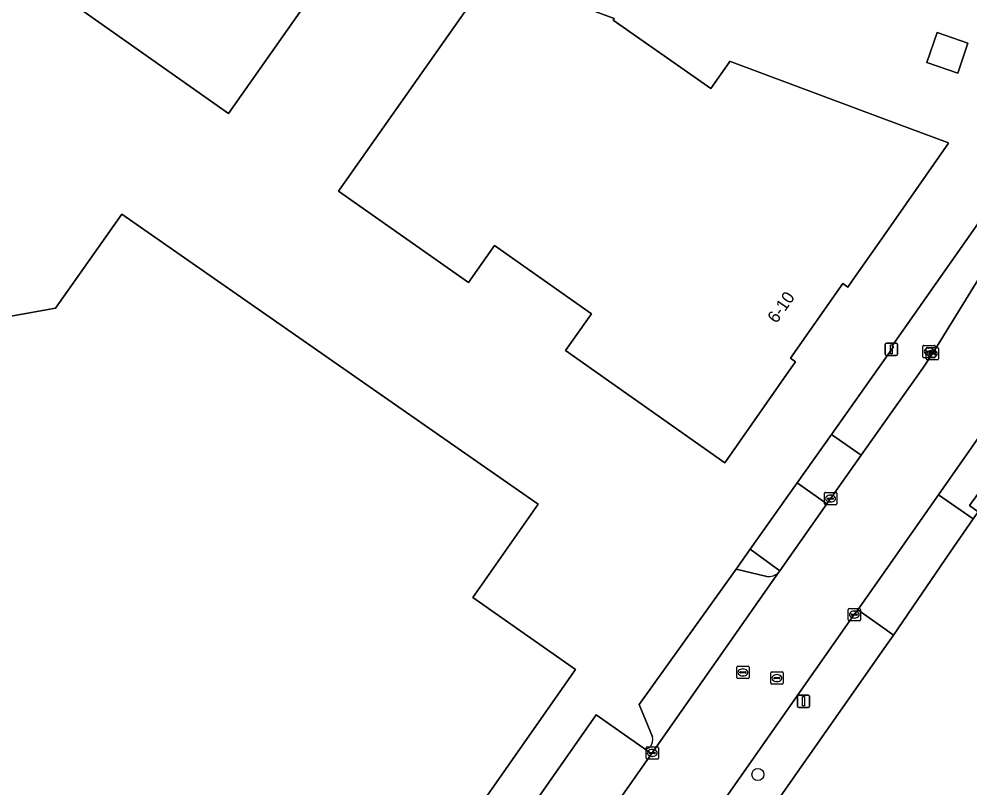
# Model space of a CAD drawing. Extents: x 155018 to 156648, y 383979 to 385733.
# Drawn here: x 155429.7 to 155506.9, y 385085.5 to 385148 of the extents above; entities that cross this region are included whole.
import ezdxf

# ---------------------------------------------------------------- set-up
doc = ezdxf.new("R2010")
doc.units = 0
for name, color, linetype in [('IMGEO_Boom', 7, 'Continuous'), ('IMGEO_Erf', 7, 'Continuous'), ('IMGEO_Kolk', 7, 'Continuous'), ('IMGEO_Lichtmast', 7, 'Continuous'), ('IMGEO_Pand', 7, 'Continuous'), ('IMGEO_Pand_nummerreeks', 7, 'Continuous'), ('IMGEO_Parkeervlak_open', 7, 'Continuous'), ('IMGEO_Rijbaan_lokaal_gesloten', 7, 'Continuous'), ('IMGEO_Rijbaan_lokaal_open', 7, 'Continuous'), ('IMGEO_Rioolput', 7, 'Continuous'), ('IMGEO_Voetpad_open', 7, 'Continuous')]:
    doc.layers.add(name, color=color, linetype=linetype)

msp = doc.modelspace()

# ---------------------------------------------------------------- linework, layer by layer
at = {"layer": 'IMGEO_Boom'}
msp.add_circle((155489.766, 385086.611), 0.489, dxfattribs=at)
at = {"layer": 'IMGEO_Erf'}
for points in [[(155413.901, 385195.202), (155443.274, 385174.657), (155442.008, 385172.848), (155454.266, 385164.273), (155459.175, 385158.044), (155446.72, 385140.342), (155440.509, 385144.723), (155428.297, 385153.343), (155424.544, 385148.026), (155385.157, 385092.221), (155368.632, 385103.714), (155368.071, 385102.911), (155349.266, 385116.068), (155349.893, 385116.961), (155349.496, 385119.02), (155348.617, 385119.628), (155359.431, 385135.082), (155364.489, 385131.542), (155367.766, 385129.249), (155370.632, 385133.346)], [(155468.14, 385151.739), (155478.07, 385148.075), (155478.004, 385147.93), (155485.935, 385142.376), (155487.428, 385144.488), (155487.454, 385144.588), (155500, 385139.914), (155505.174, 385137.986), (155505.266, 385137.927), (155500, 385130.399), (155497.444, 385126.745), (155497.088, 385126.236), (155496.678, 385126.524), (155492.417, 385120.452), (155492.827, 385120.164), (155492.475, 385119.66), (155487.089, 385111.95), (155474.126, 385121.065), (155476.237, 385124.066), (155468.354, 385129.61), (155466.243, 385126.609), (155455.672, 385134.024)], [(155504.353, 385146.913), (155506.838, 385146.045), (155506.025, 385143.622), (155503.492, 385144.492)]]:
    msp.add_lwpolyline(points, close=True, dxfattribs=at)
for points in [[(155481.197, 385089.662), (155480.122, 385092.288), (155488.002, 385103.313), (155488.181, 385103.567), (155489.14, 385104.923), (155492.958, 385110.322), (155495.738, 385114.252), (155500, 385120.251), (155500.792, 385121.366), (155500.688, 385121.46), (155508.553, 385132.633), (155507.992, 385133.028), (155510.135, 385136.111), (155510.234, 385136.1), (155510.941, 385137.798), (155512.006, 385141.006), (155512.546, 385141.983), (155514.242, 385146.673), (155513.774, 385146.868), (155529.193, 385190.291)], [(155411.431, 385120.683), (155432.666, 385124.506), (155438.045, 385132.168), (155467.798, 385111.439), (155471.901, 385108.581), (155466.588, 385100.985), (155474.93, 385095.15), (155457.22, 385069.83), (155453.46, 385069.27), (155453.5, 385068.76)], [(155508.732, 385110.886), (155506.969, 385108.464), (155507.669, 385107.967), (155507.272, 385107.392), (155505.402, 385104.686), (155500.791, 385097.946), (155500, 385096.817), (155478.381, 385065.973), (155465.216, 385047.189), (155455.905, 385033.942)], [(155469.031, 385072.592), (155465.262, 385075.236), (155476.621, 385091.468), (155480.435, 385088.767)]]:
    msp.add_lwpolyline(points, dxfattribs=at)
for centre, radius, start, end in [((155480.307, 385089.443), 0.917, 322.49003, 13.81442), ((155480.671, 385089.151), 0.45, 238.43948, 323.84909)]:
    msp.add_arc(centre, radius, start, end, dxfattribs=at)
at = {"layer": 'IMGEO_Kolk'}
for p, q in [((155503.188, 385120.565), (155503.188, 385121.417)), ((155503.263, 385121.491), (155504.115, 385121.491)), ((155503.44, 385120.389), (155503.44, 385121.241)), ((155503.447, 385120.985), (155503.447, 385120.997)), ((155503.885, 385120.948), (155503.487, 385120.948)), ((155503.49, 385121.034), (155503.888, 385121.034)), ((155503.515, 385121.315), (155504.367, 385121.315)), ((155503.676, 385121.271), (155503.701, 385121.271)), ((155503.699, 385120.809), (155503.699, 385120.821)), ((155504.137, 385120.772), (155503.739, 385120.772)), ((155503.742, 385120.858), (155504.14, 385120.858)), ((155503.928, 385121.095), (155503.953, 385121.095)), ((155503.931, 385120.997), (155503.931, 385120.985)), ((155504.183, 385120.821), (155504.183, 385120.809)), ((155504.189, 385121.417), (155504.189, 385120.565)), ((155504.441, 385121.241), (155504.441, 385120.389)), ((155504.115, 385120.491), (155503.263, 385120.491)), ((155504.367, 385120.315), (155503.515, 385120.315)), ((155503.699, 385120.711), (155503.674, 385120.711)), ((155503.951, 385120.535), (155503.926, 385120.535)), ((155495.176, 385108.615), (155495.176, 385109.467)), ((155495.251, 385109.541), (155496.103, 385109.541)), ((155495.664, 385109.321), (155495.689, 385109.321)), ((155496.177, 385109.467), (155496.177, 385108.615)), ((155496.103, 385108.541), (155495.251, 385108.541)), ((155495.435, 385109.035), (155495.435, 385109.047)), ((155495.873, 385108.998), (155495.475, 385108.998)), ((155495.478, 385109.084), (155495.876, 385109.084)), ((155495.687, 385108.761), (155495.662, 385108.761)), ((155495.919, 385109.047), (155495.919, 385109.035)), ((155497.104, 385099.178), (155497.104, 385100.03)), ((155497.179, 385100.104), (155498.031, 385100.104)), ((155498.105, 385100.03), (155498.105, 385099.178)), ((155497.363, 385099.598), (155497.363, 385099.61)), ((155497.801, 385099.561), (155497.403, 385099.561)), ((155497.406, 385099.647), (155497.804, 385099.647)), ((155497.615, 385099.324), (155497.59, 385099.324)), ((155497.592, 385099.884), (155497.617, 385099.884)), ((155497.847, 385099.61), (155497.847, 385099.598)), ((155498.031, 385099.104), (155497.179, 385099.104)), ((155480.678, 385087.935), (155480.678, 385088.787)), ((155480.753, 385088.861), (155481.605, 385088.861)), ((155480.937, 385088.355), (155480.937, 385088.367)), ((155480.98, 385088.404), (155481.378, 385088.404)), ((155481.166, 385088.641), (155481.191, 385088.641)), ((155481.421, 385088.367), (155481.421, 385088.355)), ((155481.679, 385088.787), (155481.679, 385087.935)), ((155481.605, 385087.861), (155480.753, 385087.861)), ((155481.375, 385088.318), (155480.977, 385088.318)), ((155481.189, 385088.081), (155481.164, 385088.081))]:
    msp.add_line(p, q, dxfattribs=at)
for points in [[(155503.188, 385120.565), (155503.188, 385121.417)], [(155503.263, 385121.491), (155504.115, 385121.491)], [(155503.44, 385120.389), (155503.44, 385121.241)], [(155503.515, 385121.315), (155504.367, 385121.315)], [(155504.189, 385121.417), (155504.189, 385120.565)], [(155504.441, 385121.241), (155504.441, 385120.389)], [(155504.115, 385120.491), (155503.263, 385120.491)], [(155504.367, 385120.315), (155503.515, 385120.315)], [(155495.176, 385108.615), (155495.176, 385109.467)], [(155495.251, 385109.541), (155496.103, 385109.541)], [(155496.177, 385109.467), (155496.177, 385108.615)], [(155496.103, 385108.541), (155495.251, 385108.541)], [(155497.104, 385099.178), (155497.104, 385100.03)], [(155497.179, 385100.104), (155498.031, 385100.104)], [(155498.105, 385100.03), (155498.105, 385099.178)], [(155498.031, 385099.104), (155497.179, 385099.104)], [(155480.678, 385087.935), (155480.678, 385088.787)], [(155480.753, 385088.861), (155481.605, 385088.861)], [(155481.679, 385088.787), (155481.679, 385087.935)], [(155481.605, 385087.861), (155480.753, 385087.861)]]:
    msp.add_lwpolyline(points, dxfattribs=at)
for centre, radius, start, end in [((155503.265, 385121.415), 0.0765, 91.55205, 178.44795), ((155503.265, 385121.415), 0.0765, 91.55205, 178.44795), ((155503.517, 385121.239), 0.0765, 91.55205, 178.44795), ((155503.517, 385121.239), 0.0765, 91.55205, 178.44795), ((155503.487, 385120.994), 0.0403, 85.87752, 175.75265), ((155503.484, 385120.984), 0.0366, 178.93798, 274.71019), ((155503.739, 385120.818), 0.0403, 85.87752, 175.75265), ((155503.736, 385120.808), 0.0366, 178.93798, 274.71019), ((155503.888, 385120.991), 0.043, 264.86636, 352.45326), ((155503.892, 385120.996), 0.0386, 1.73085, 96.63898), ((155504.113, 385121.415), 0.0765, 1.55205, 88.44795), ((155504.113, 385121.415), 0.0765, 1.55205, 88.44795), ((155504.14, 385120.815), 0.043, 264.86636, 352.45326), ((155504.144, 385120.82), 0.0386, 1.73085, 96.63898), ((155504.365, 385121.239), 0.0765, 1.55205, 88.44795), ((155504.365, 385121.239), 0.0765, 1.55205, 88.44795), ((155503.265, 385120.567), 0.0765, 181.55205, 268.44795), ((155503.265, 385120.567), 0.0765, 181.55205, 268.44795), ((155503.517, 385120.391), 0.0765, 181.55205, 268.44795), ((155503.517, 385120.391), 0.0765, 181.55205, 268.44795), ((155504.113, 385120.567), 0.0765, 271.55205, 358.44795), ((155504.113, 385120.567), 0.0765, 271.55205, 358.44795), ((155504.365, 385120.391), 0.0765, 271.55205, 358.44795), ((155504.365, 385120.391), 0.0765, 271.55205, 358.44795), ((155495.253, 385109.465), 0.0765, 91.55205, 178.44795), ((155495.253, 385109.465), 0.0765, 91.55205, 178.44795), ((155496.101, 385109.465), 0.0765, 1.55205, 88.44795), ((155496.101, 385109.465), 0.0765, 1.55205, 88.44795), ((155495.253, 385108.617), 0.0765, 181.55205, 268.44795), ((155495.253, 385108.617), 0.0765, 181.55205, 268.44795), ((155495.475, 385109.044), 0.0403, 85.87752, 175.75265), ((155495.472, 385109.034), 0.0366, 178.93798, 274.71019), ((155495.876, 385109.041), 0.043, 264.86636, 352.45326), ((155495.88, 385109.046), 0.0386, 1.73085, 96.63898), ((155496.101, 385108.617), 0.0765, 271.55205, 358.44795), ((155496.101, 385108.617), 0.0765, 271.55205, 358.44795), ((155497.181, 385100.028), 0.0765, 91.55205, 178.44795), ((155497.181, 385100.028), 0.0765, 91.55205, 178.44795), ((155498.029, 385100.028), 0.0765, 1.55205, 88.44795), ((155498.029, 385100.028), 0.0765, 1.55205, 88.44795), ((155497.181, 385099.18), 0.0765, 181.55205, 268.44795), ((155497.181, 385099.18), 0.0765, 181.55205, 268.44795), ((155497.403, 385099.607), 0.0403, 85.87752, 175.75265), ((155497.4, 385099.597), 0.0366, 178.93798, 274.71019), ((155497.804, 385099.604), 0.043, 264.86636, 352.45326), ((155497.808, 385099.609), 0.0386, 1.73085, 96.63898), ((155498.029, 385099.18), 0.0765, 271.55205, 358.44795), ((155498.029, 385099.18), 0.0765, 271.55205, 358.44795), ((155480.755, 385088.785), 0.0765, 91.55205, 178.44795), ((155480.755, 385088.785), 0.0765, 91.55205, 178.44795), ((155480.977, 385088.364), 0.0403, 85.87752, 175.75265), ((155480.974, 385088.354), 0.0366, 178.93798, 274.71019), ((155481.378, 385088.361), 0.043, 264.86636, 352.45326), ((155481.382, 385088.366), 0.0386, 1.73085, 96.63898), ((155481.603, 385088.785), 0.0765, 1.55205, 88.44795), ((155481.603, 385088.785), 0.0765, 1.55205, 88.44795), ((155480.755, 385087.937), 0.0765, 181.55205, 268.44795), ((155480.755, 385087.937), 0.0765, 181.55205, 268.44795), ((155481.603, 385087.937), 0.0765, 271.55205, 358.44795), ((155481.603, 385087.937), 0.0765, 271.55205, 358.44795)]:
    msp.add_arc(centre, radius, start, end, dxfattribs=at)
for centre, major_axis, ratio, start_param, end_param in [((155503.675, 385120.991), (-0.387, 0.002), 0.722429, 4.712389, 7.853982), ((155503.927, 385120.815), (-0.387, 0.002), 0.722429, 4.712389, 7.853982), ((155503.7, 385120.991), (-0.39, 0.002), 0.717154, 1.570796, 4.712389), ((155503.952, 385120.815), (-0.39, 0.002), 0.717154, 1.570796, 4.712389), ((155495.663, 385109.041), (-0.387, 0.002), 0.722429, 4.712389, 7.853982), ((155495.688, 385109.041), (-0.39, 0.002), 0.717154, 1.570796, 4.712389), ((155497.591, 385099.604), (-0.387, 0.002), 0.722429, 4.712389, 7.853982), ((155497.616, 385099.604), (-0.39, 0.002), 0.717154, 1.570796, 4.712389), ((155481.165, 385088.361), (-0.387, 0.002), 0.722429, 4.712389, 7.853982), ((155481.19, 385088.361), (-0.39, 0.002), 0.717154, 1.570796, 4.712389)]:
    msp.add_ellipse(centre, major_axis=major_axis, ratio=ratio, start_param=start_param, end_param=end_param, dxfattribs=at)
at = {"layer": 'IMGEO_Lichtmast'}
for p, q in [((155500.118, 385120.769), (155500.118, 385121.569)), ((155500.118, 385121.569), (155500.118, 385120.769)), ((155500.218, 385121.669), (155501.008, 385121.669)), ((155501.008, 385121.669), (155500.218, 385121.669)), ((155501.108, 385121.569), (155501.108, 385120.769)), ((155501.108, 385120.769), (155501.108, 385121.569)), ((155501.008, 385120.669), (155500.218, 385120.669)), ((155500.218, 385120.669), (155501.008, 385120.669)), ((155492.982, 385092.166), (155492.982, 385092.966)), ((155492.982, 385092.966), (155492.982, 385092.166)), ((155493.082, 385093.066), (155493.872, 385093.066)), ((155493.872, 385093.066), (155493.082, 385093.066)), ((155493.972, 385092.966), (155493.972, 385092.166)), ((155493.972, 385092.166), (155493.972, 385092.966)), ((155493.872, 385092.066), (155493.082, 385092.066)), ((155493.082, 385092.066), (155493.872, 385092.066))]:
    msp.add_line(p, q, dxfattribs=at)
for points in [[(155500.538, 385121.544), (155500.688, 385121.544), (155500.688, 385120.794), (155500.538, 385120.794), (155500.538, 385121.544)], [(155493.402, 385092.941), (155493.552, 385092.941), (155493.552, 385092.191), (155493.402, 385092.191), (155493.402, 385092.941)]]:
    msp.add_lwpolyline(points, dxfattribs=at)
for centre, start, end in [((155500.218, 385121.569), 90, 180), ((155500.218, 385121.569), 90, 180), ((155501.008, 385121.569), 0, 90), ((155501.008, 385121.569), 360, 90), ((155500.218, 385120.769), 180, 270), ((155500.218, 385120.769), 180, 270), ((155501.008, 385120.769), 270, 0), ((155501.008, 385120.769), 270, 0), ((155493.082, 385092.966), 90, 180), ((155493.082, 385092.966), 90, 180), ((155493.872, 385092.966), 0, 90), ((155493.872, 385092.966), 360, 90), ((155493.082, 385092.166), 180, 270), ((155493.082, 385092.166), 180, 270), ((155493.872, 385092.166), 270, 0), ((155493.872, 385092.166), 270, 0)]:
    msp.add_arc(centre, 0.1, start, end, dxfattribs=at)
at = {"layer": 'IMGEO_Pand'}
for points in [[(155442.008, 385172.848), (155428.297, 385153.343), (155440.509, 385144.723), (155446.72, 385140.342), (155459.175, 385158.044), (155454.266, 385164.273)], [(155497.444, 385126.745), (155500, 385130.399), (155505.266, 385137.927), (155505.174, 385137.986), (155500, 385139.914), (155487.454, 385144.588), (155487.428, 385144.488), (155485.935, 385142.376), (155478.004, 385147.93), (155478.07, 385148.075), (155468.14, 385151.739), (155455.672, 385134.024), (155466.243, 385126.609), (155468.354, 385129.61), (155476.237, 385124.066), (155474.126, 385121.065), (155487.089, 385111.95), (155492.475, 385119.66), (155492.827, 385120.164), (155492.417, 385120.452), (155496.678, 385126.524), (155497.088, 385126.236)], [(155506.025, 385143.622), (155506.838, 385146.045), (155504.353, 385146.913), (155503.492, 385144.492)]]:
    msp.add_lwpolyline(points, close=True, dxfattribs=at)
msp.add_lwpolyline([(155453.5, 385068.76), (155453.46, 385069.27), (155457.22, 385069.83), (155474.93, 385095.15), (155466.588, 385100.985), (155471.901, 385108.581), (155467.798, 385111.439), (155438.045, 385132.168), (155432.666, 385124.506), (155411.431, 385120.683), (155384.95, 385082.874), (155382.08, 385078.78), (155407.39, 385061.04), (155411.11, 385061.77), (155411.2, 385061.27)], dxfattribs=at)
at = {"layer": 'IMGEO_Parkeervlak_open'}
msp.add_lwpolyline([(155467.49, 385070.365), (155463.698, 385073.028), (155451.939, 385056.265), (155455.702, 385053.635), (155456.449, 385053.113), (155481.116, 385088.283), (155480.435, 385088.767), (155476.621, 385091.468), (155465.262, 385075.236), (155469.031, 385072.592)], dxfattribs=at)
at = {"layer": 'IMGEO_Rijbaan_lokaal_gesloten'}
for points in [[(155497.6, 385099.605), (155497.894, 385100), (155500, 385103.003), (155504.455, 385109.355), (155509.68, 385116.82), (155513.64, 385123.17), (155517.035, 385129.07), (155519.387, 385133.898), (155520.017, 385135.192), (155521.4, 385138.486), (155522.69, 385142.05), (155523.463, 385144.211), (155526.463, 385152.665), (155530.454, 385163.868), (155534.193, 385174.381), (155539.728, 385189.975), (155540.748, 385192.836), (155534.179, 385195.179), (155532.098, 385189.247), (155531.642, 385187.947), (155515.445, 385142.497)], [(155507.876, 385127.146), (155504.079, 385121.005), (155503.176, 385119.645), (155500, 385115.169), (155498.158, 385112.573), (155495.376, 385108.61), (155491.551, 385103.161), (155491.432, 385103.018), (155481.116, 385088.283), (155456.449, 385053.113), (155451.957, 385046.708), (155447.504, 385040.321)], [(155452.761, 385035.606), (155462.333, 385049.231), (155475.481, 385068.042), (155475.777, 385068.485), (155497.6, 385099.605)]]:
    msp.add_lwpolyline(points, dxfattribs=at)
at = {"layer": 'IMGEO_Rijbaan_lokaal_open'}
for points in [[(155495.376, 385108.61), (155492.958, 385110.322), (155489.14, 385104.923), (155491.551, 385103.161)], [(155505.402, 385104.686), (155507.272, 385107.392), (155504.455, 385109.355), (155500, 385103.003), (155497.894, 385100), (155500, 385098.507), (155500.791, 385097.946)]]:
    msp.add_lwpolyline(points, close=True, dxfattribs=at)
for points in [[(155490.505, 385102.713), (155488.002, 385103.313), (155480.122, 385092.288), (155481.197, 385089.662)], [(155480.435, 385088.767), (155481.116, 385088.283), (155491.432, 385103.018)]]:
    msp.add_lwpolyline(points, dxfattribs=at)
for centre, radius, start, end in [((155490.67, 385103.774), 1.073, 261.17279, 315.25152), ((155480.307, 385089.443), 0.917, 322.49003, 13.81442), ((155480.671, 385089.151), 0.45, 238.43948, 323.84909)]:
    msp.add_arc(centre, radius, start, end, dxfattribs=at)
at = {"layer": 'IMGEO_Rioolput'}
for p, q in [((155488.049, 385094.482), (155488.049, 385095.334)), ((155488.124, 385095.408), (155488.976, 385095.408)), ((155489.05, 385095.334), (155489.05, 385094.482)), ((155488.308, 385094.902), (155488.308, 385094.914)), ((155488.746, 385094.865), (155488.348, 385094.865)), ((155488.351, 385094.951), (155488.749, 385094.951)), ((155488.56, 385094.628), (155488.535, 385094.628)), ((155488.537, 385095.188), (155488.562, 385095.188)), ((155488.792, 385094.914), (155488.792, 385094.902)), ((155490.813, 385094.02), (155490.813, 385094.872)), ((155490.888, 385094.946), (155491.74, 385094.946)), ((155491.301, 385094.726), (155491.326, 385094.726)), ((155491.814, 385094.872), (155491.814, 385094.02)), ((155488.976, 385094.408), (155488.124, 385094.408)), ((155491.74, 385093.946), (155490.888, 385093.946)), ((155491.072, 385094.44), (155491.072, 385094.452)), ((155491.51, 385094.403), (155491.112, 385094.403)), ((155491.115, 385094.489), (155491.513, 385094.489)), ((155491.324, 385094.166), (155491.299, 385094.166)), ((155491.556, 385094.452), (155491.556, 385094.44))]:
    msp.add_line(p, q, dxfattribs=at)
for points in [[(155488.049, 385094.482), (155488.049, 385095.334)], [(155488.124, 385095.408), (155488.976, 385095.408)], [(155489.05, 385095.334), (155489.05, 385094.482)], [(155490.813, 385094.02), (155490.813, 385094.872)], [(155490.888, 385094.946), (155491.74, 385094.946)], [(155491.814, 385094.872), (155491.814, 385094.02)], [(155488.976, 385094.408), (155488.124, 385094.408)], [(155491.74, 385093.946), (155490.888, 385093.946)]]:
    msp.add_lwpolyline(points, dxfattribs=at)
for centre, radius, start, end in [((155488.126, 385095.332), 0.0765, 91.55205, 178.44795), ((155488.126, 385095.332), 0.0765, 91.55205, 178.44795), ((155488.974, 385095.332), 0.0765, 1.55205, 88.44795), ((155488.974, 385095.332), 0.0765, 1.55205, 88.44795), ((155488.348, 385094.911), 0.0403, 85.87752, 175.75265), ((155488.345, 385094.901), 0.0366, 178.93798, 274.71019), ((155488.749, 385094.908), 0.043, 264.86636, 352.45326), ((155488.753, 385094.913), 0.0386, 1.73085, 96.63898), ((155490.89, 385094.87), 0.0765, 91.55205, 178.44795), ((155490.89, 385094.87), 0.0765, 91.55205, 178.44795), ((155491.738, 385094.87), 0.0765, 1.55205, 88.44795), ((155491.738, 385094.87), 0.0765, 1.55205, 88.44795), ((155488.126, 385094.484), 0.0765, 181.55205, 268.44795), ((155488.126, 385094.484), 0.0765, 181.55205, 268.44795), ((155488.974, 385094.484), 0.0765, 271.55205, 358.44795), ((155488.974, 385094.484), 0.0765, 271.55205, 358.44795), ((155490.89, 385094.022), 0.0765, 181.55205, 268.44795), ((155490.89, 385094.022), 0.0765, 181.55205, 268.44795), ((155491.112, 385094.449), 0.0403, 85.87752, 175.75265), ((155491.109, 385094.439), 0.0366, 178.93798, 274.71019), ((155491.513, 385094.446), 0.043, 264.86636, 352.45326), ((155491.517, 385094.451), 0.0386, 1.73085, 96.63898), ((155491.738, 385094.022), 0.0765, 271.55205, 358.44795), ((155491.738, 385094.022), 0.0765, 271.55205, 358.44795)]:
    msp.add_arc(centre, radius, start, end, dxfattribs=at)
for centre, major_axis, ratio, start_param, end_param in [((155488.536, 385094.908), (-0.387, 0.002), 0.722429, 4.712389, 7.853982), ((155488.561, 385094.908), (-0.39, 0.002), 0.717154, 1.570796, 4.712389), ((155491.3, 385094.446), (-0.387, 0.002), 0.722429, 4.712389, 7.853982), ((155491.325, 385094.446), (-0.39, 0.002), 0.717154, 1.570796, 4.712389)]:
    msp.add_ellipse(centre, major_axis=major_axis, ratio=ratio, start_param=start_param, end_param=end_param, dxfattribs=at)
at = {"layer": 'IMGEO_Voetpad_open'}
for points in [[(155514.513, 385140.064), (155512.574, 385140.779), (155512.006, 385141.006), (155510.941, 385137.798), (155510.234, 385136.1), (155510.135, 385136.111), (155507.992, 385133.028), (155508.553, 385132.633), (155500.688, 385121.46), (155500.792, 385121.366), (155500, 385120.251), (155495.738, 385114.252), (155498.158, 385112.573), (155500, 385115.169), (155503.176, 385119.645), (155504.079, 385121.005), (155507.876, 385127.146)], [(155521.682, 385132.711), (155519.387, 385133.898), (155517.035, 385129.07), (155513.64, 385123.17), (155509.68, 385116.82), (155504.455, 385109.355), (155507.272, 385107.392), (155507.669, 385107.967), (155506.969, 385108.464), (155508.732, 385110.886)], [(155491.432, 385103.018), (155491.551, 385103.161), (155489.14, 385104.923), (155488.181, 385103.567), (155488.002, 385103.313), (155490.505, 385102.713)]]:
    msp.add_lwpolyline(points, dxfattribs=at)
for points in [[(155498.158, 385112.573), (155495.738, 385114.252), (155492.958, 385110.322), (155495.376, 385108.61)], [(155475.481, 385068.042), (155478.381, 385065.973), (155500, 385096.817), (155500.791, 385097.946), (155500, 385098.507), (155497.894, 385100), (155497.6, 385099.605), (155475.777, 385068.485)]]:
    msp.add_lwpolyline(points, close=True, dxfattribs=at)
msp.add_arc((155490.67, 385103.774), 1.073, 261.17279, 315.25152, dxfattribs=at)

# ---------------------------------------------------------------- texts
at = {"layer": 'IMGEO_Pand_nummerreeks'}
msp.add_text('6-10', height=1, rotation=54.94091, dxfattribs=at).set_placement((155491.279, 385123.217))

doc.saveas('drawing.dxf')
